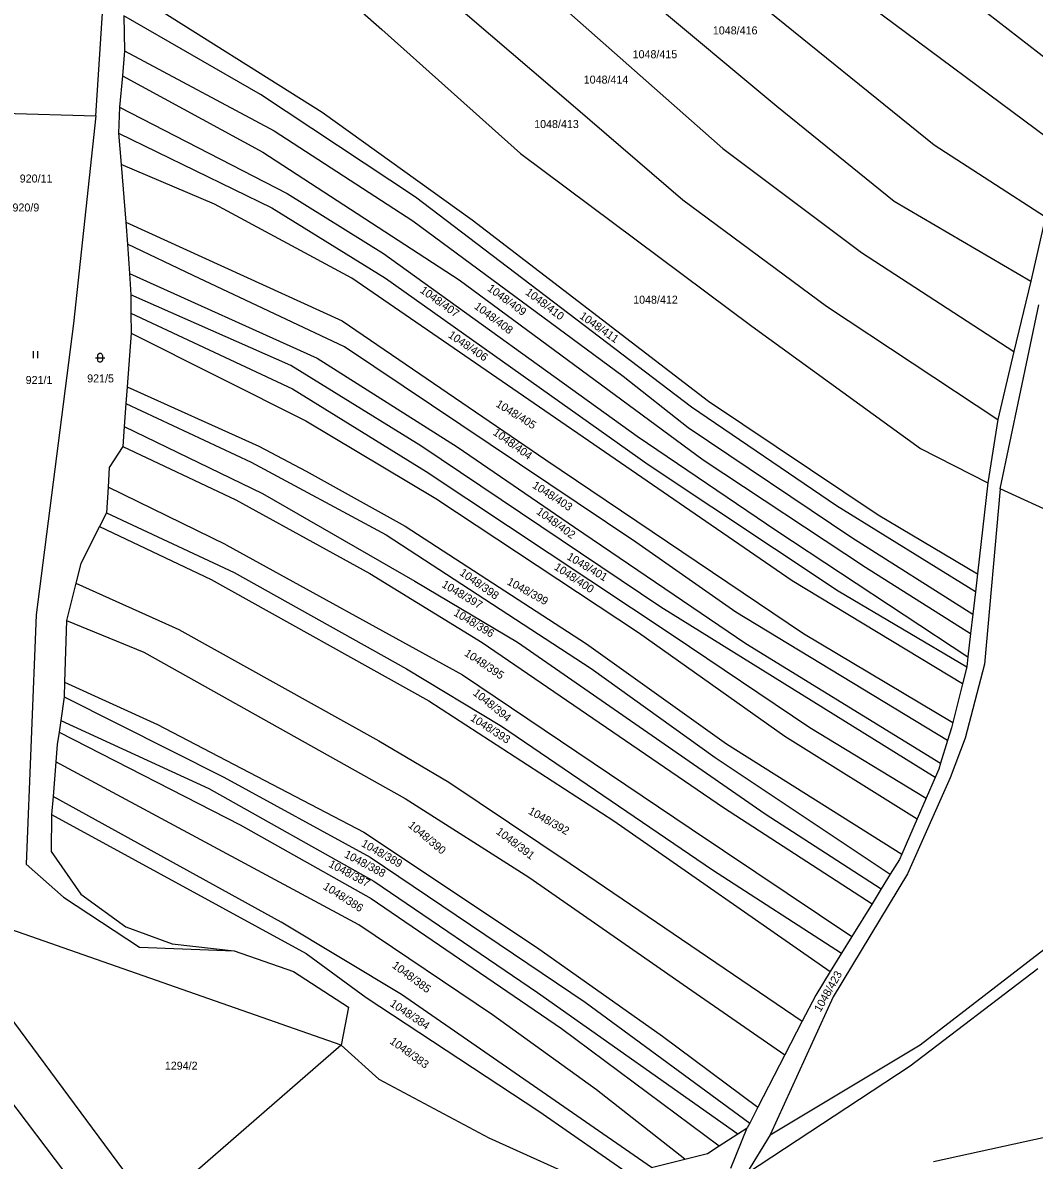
# Model space of a CAD drawing. Extents: x -580630 to -576196, y -1189024 to -1183567.
# Drawn here: x -577874.8 to -577659.8, y -1186685.8 to -1186444.2 of the extents above; entities that cross this region are included whole.
import ezdxf

# ---------------------------------------------------------------- set-up
doc = ezdxf.new("R2010")
doc.units = 0
for name, color, linetype in [('Vrstva 1', 7, 'Continuous'), ('Vrstva 16', 7, 'Continuous'), ('Vrstva 18', 7, 'Continuous'), ('Vrstva 25', 7, 'Continuous'), ('Vrstva 6', 7, 'Continuous')]:
    doc.layers.add(name, color=color, linetype=linetype)

msp = doc.modelspace()

# ---------------------------------------------------------------- linework, layer by layer
at = {"layer": 'Vrstva 1'}
for p, q in [((-577859.22, -1186463.95), (-577855.05, -1186398.23)), ((-577853.26, -1186442.7), (-577853.11, -1186450.13)), ((-577853.11, -1186450.13), (-577853.59, -1186455.45)), ((-577853.59, -1186455.45), (-577854.18, -1186462.09)), ((-577878.88, -1186463.42), (-577859.22, -1186463.95)), ((-577859.22, -1186463.95), (-577864.01, -1186508.08)), ((-577854.18, -1186462.09), (-577854.44, -1186467.67)), ((-577854.44, -1186467.67), (-577853.88, -1186474.32)), ((-577853.88, -1186474.32), (-577852.85, -1186486.55)), ((-577852.85, -1186486.55), (-577852.53, -1186491.24)), ((-577852.53, -1186491.24), (-577852.1, -1186497.48)), ((-577852.1, -1186497.48), (-577851.79, -1186501.97)), ((-577851.79, -1186501.97), (-577851.78, -1186505.89)), ((-577851.78, -1186505.89), (-577851.76, -1186510.12)), ((-577864.01, -1186508.08), (-577871.88, -1186569.94)), ((-577851.76, -1186510.12), (-577852.58, -1186521.49)), ((-577852.58, -1186521.49), (-577852.84, -1186525.09)), ((-577852.84, -1186525.09), (-577853.19, -1186529.98)), ((-577853.19, -1186529.98), (-577853.49, -1186534.17)), ((-577853.49, -1186534.17), (-577856.41, -1186538.69)), ((-577856.41, -1186538.69), (-577856.64, -1186542.85)), ((-577856.64, -1186542.85), (-577856.94, -1186548.26)), ((-577856.94, -1186548.26), (-577858.44, -1186551.22)), ((-577858.44, -1186551.22), (-577862.39, -1186559.03)), ((-577862.39, -1186559.03), (-577863.45, -1186563.21)), ((-577863.45, -1186563.21), (-577865.45, -1186571.12)), ((-577871.88, -1186569.94), (-577874.01, -1186622.9)), ((-577865.45, -1186571.12), (-577865.87, -1186584.25)), ((-577865.87, -1186584.25), (-577865.97, -1186587.39)), ((-577865.97, -1186587.39), (-577866.7, -1186592.43)), ((-577866.7, -1186592.43), (-577867.06, -1186594.9)), ((-577867.06, -1186594.9), (-577867.43, -1186597.49)), ((-577867.43, -1186597.49), (-577867.73, -1186601.18)), ((-577867.73, -1186601.18), (-577868.32, -1186608.51)), ((-577868.32, -1186608.51), (-577868.63, -1186612.38)), ((-577868.63, -1186612.38), (-577868.76, -1186620.22)), ((-577868.76, -1186620.22), (-577862.39, -1186629.26)), ((-577874.01, -1186622.9), (-577866.1, -1186629.9)), ((-577866.1, -1186629.9), (-577849.97, -1186640.56)), ((-577862.39, -1186629.26), (-577852.84, -1186636.25)), ((-577807.14, -1186661.37), (-577883.51, -1186634.65)), ((-577852.84, -1186636.25), (-577843.01, -1186639.84)), ((-577843.01, -1186639.84), (-577829.86, -1186641.3)), ((-577849.97, -1186640.56), (-577829.86, -1186641.3)), ((-577829.86, -1186641.3), (-577817.24, -1186645.69)), ((-577817.24, -1186645.69), (-577805.55, -1186653.27)), ((-577847.2, -1186696.2), (-577879.08, -1186653.13)), ((-577805.55, -1186653.27), (-577807.14, -1186661.37)), ((-577807.14, -1186661.37), (-577847.2, -1186696.2)), ((-577807.14, -1186661.37), (-577799.11, -1186668.55)), ((-577842.78, -1186718.77), (-577885, -1186663.02)), ((-577799.11, -1186668.55), (-577775.73, -1186681.05)), ((-577775.73, -1186681.05), (-577749.96, -1186692.62))]:
    msp.add_line(p, q, dxfattribs=at)
at = {"layer": 'Vrstva 25'}
for p, q in [((-577872.55, -1186513.91), (-577872.55, -1186515.41)), ((-577871.55, -1186515.41), (-577871.55, -1186513.91))]:
    msp.add_line(p, q, dxfattribs=at)
msp.add_lwpolyline([(-577858.84, -1186514.84), (-577858.74, -1186514.55), (-577858.49, -1186514.37), (-577858.18, -1186514.37), (-577857.93, -1186514.55), (-577857.83, -1186514.84), (-577857.83, -1186515.84), (-577857.93, -1186516.13), (-577858.18, -1186516.31), (-577858.49, -1186516.31), (-577858.74, -1186516.13), (-577858.84, -1186515.84)], close=True, dxfattribs=at)
msp.add_lwpolyline([(-577859.34, -1186515.34), (-577858.07, -1186515.34), (-577857.34, -1186515.34)], dxfattribs=at)
at = {"layer": 'Vrstva 6'}
for p, q in [((-577793.75, -1186395.8), (-577714.53, -1186461.91)), ((-577807.04, -1186399.23), (-577726.02, -1186470.93)), ((-577824.91, -1186404.3), (-577757.34, -1186462.16)), ((-577837.71, -1186410.74), (-577798.49, -1186445.63)), ((-577648.78, -1186458.48), (-577691.75, -1186425.18)), ((-577705.7, -1186432.42), (-577653.48, -1186471.22)), ((-577853.38, -1186436.57), (-577811.17, -1186463.18)), ((-577719.89, -1186438.75), (-577681.11, -1186470.11)), ((-577824.25, -1186459.42), (-577853.26, -1186442.7)), ((-577798.49, -1186445.63), (-577769, -1186471.95)), ((-577853.11, -1186450.13), (-577821.34, -1186467.13)), ((-577853.59, -1186455.45), (-577823.72, -1186471.65)), ((-577791.31, -1186481.22), (-577824.25, -1186459.42)), ((-577854.18, -1186462.09), (-577818.58, -1186480.43)), ((-577811.17, -1186463.18), (-577779.29, -1186486.04)), ((-577757.34, -1186462.16), (-577734.49, -1186481.83)), ((-577714.53, -1186461.91), (-577689.62, -1186482.09)), ((-577854.44, -1186467.67), (-577821.83, -1186483.53)), ((-577821.34, -1186467.13), (-577791.85, -1186486.27)), ((-577726.02, -1186470.93), (-577696.53, -1186492.99)), ((-577681.11, -1186470.11), (-577657.44, -1186485.43)), ((-577823.72, -1186471.65), (-577782.01, -1186498.77)), ((-577769, -1186471.95), (-577719.85, -1186508.64)), ((-577834.05, -1186482.73), (-577853.88, -1186474.32)), ((-577818.58, -1186480.43), (-577798.12, -1186493.19)), ((-577804.83, -1186498.41), (-577834.05, -1186482.73)), ((-577732.63, -1186525.82), (-577791.31, -1186481.22)), ((-577734.49, -1186481.83), (-577703.98, -1186504.37)), ((-577689.62, -1186482.09), (-577660.59, -1186499.11)), ((-577821.83, -1186483.53), (-577797.66, -1186498.41)), ((-577657.44, -1186485.43), (-577660.59, -1186499.11)), ((-577852.85, -1186486.55), (-577806.9, -1186507.49)), ((-577791.85, -1186486.27), (-577747.21, -1186519.23)), ((-577779.29, -1186486.04), (-577729.08, -1186524.58)), ((-577838.55, -1186497.88), (-577852.53, -1186491.24)), ((-577696.53, -1186492.99), (-577664.17, -1186513.99)), ((-577798.12, -1186493.19), (-577744.19, -1186532)), ((-577852.1, -1186497.48), (-577812.24, -1186515.43)), ((-577806.4, -1186513.04), (-577838.55, -1186497.88)), ((-577711.31, -1186562.75), (-577804.83, -1186498.41)), ((-577797.66, -1186498.41), (-577741.87, -1186538.02)), ((-577782.01, -1186498.77), (-577730.2, -1186537.05)), ((-577660.59, -1186499.11), (-577664.17, -1186513.99)), ((-577817.82, -1186517.02), (-577851.79, -1186501.97)), ((-577703.98, -1186504.37), (-577667.54, -1186528.43)), ((-577667.06, -1186543.16), (-577658.85, -1186504.08)), ((-577851.78, -1186505.89), (-577817.45, -1186521.95)), ((-577806.9, -1186507.49), (-577763.6, -1186537)), ((-577719.85, -1186508.64), (-577684.01, -1186534.64)), ((-577851.76, -1186510.12), (-577814.59, -1186528.76)), ((-577744.5, -1186554.51), (-577806.4, -1186513.04)), ((-577664.17, -1186513.99), (-577667.54, -1186528.43)), ((-577790.19, -1186534.04), (-577817.82, -1186517.02)), ((-577812.24, -1186515.43), (-577782.49, -1186534.3)), ((-577747.21, -1186519.23), (-577733.4, -1186530.13)), ((-577852.58, -1186521.49), (-577824.61, -1186534.09)), ((-577817.45, -1186521.95), (-577789.02, -1186539.49)), ((-577852.84, -1186525.09), (-577826.23, -1186537.52)), ((-577701.82, -1186546.82), (-577732.63, -1186525.82)), ((-577729.08, -1186524.58), (-577693.03, -1186548.72)), ((-577814.59, -1186528.76), (-577786.96, -1186545.24)), ((-577667.54, -1186528.43), (-577669.71, -1186541.89)), ((-577853.19, -1186529.98), (-577823.83, -1186544.17)), ((-577733.4, -1186530.13), (-577698.6, -1186553.52)), ((-577853.49, -1186534.17), (-577829.46, -1186545.51)), ((-577824.61, -1186534.09), (-577814.52, -1186539.41)), ((-577739.18, -1186568.33), (-577790.19, -1186534.04)), ((-577744.19, -1186532), (-577714.5, -1186552.11)), ((-577782.49, -1186534.3), (-577757.52, -1186551.32)), ((-577684.01, -1186534.64), (-577669.71, -1186541.89)), ((-577826.23, -1186537.52), (-577797.53, -1186552.94)), ((-577763.6, -1186537), (-577708.9, -1186573.91)), ((-577741.87, -1186538.02), (-577701.48, -1186564.87)), ((-577730.2, -1186537.05), (-577695.69, -1186559.84)), ((-577814.52, -1186539.41), (-577793.53, -1186551.1)), ((-577789.02, -1186539.49), (-577736.74, -1186574.2)), ((-577831.54, -1186555.06), (-577856.64, -1186542.85)), ((-577669.71, -1186541.89), (-577671.91, -1186561.24)), ((-577667.06, -1186543.16), (-577670.44, -1186580.46)), ((-577620.3, -1186564.71), (-577667.06, -1186543.16)), ((-577829.46, -1186545.51), (-577801.04, -1186561.19)), ((-577823.83, -1186544.17), (-577791.42, -1186562.77)), ((-577786.96, -1186545.24), (-577743.92, -1186573.69)), ((-577856.94, -1186548.26), (-577829.87, -1186560.93)), ((-577672.35, -1186565.07), (-577701.82, -1186546.82)), ((-577793.53, -1186551.1), (-577755.01, -1186576.08)), ((-577693.03, -1186548.72), (-577671.91, -1186561.24)), ((-577858.44, -1186551.22), (-577834.73, -1186562.44)), ((-577797.53, -1186552.94), (-577753.97, -1186581.37)), ((-577757.52, -1186551.32), (-577721.12, -1186576.04)), ((-577714.5, -1186552.11), (-577673.92, -1186578.85)), ((-577698.6, -1186553.52), (-577672.89, -1186569.79)), ((-577831.54, -1186555.06), (-577781.33, -1186582.7)), ((-577723.24, -1186569.39), (-577744.5, -1186554.51)), ((-577695.69, -1186559.84), (-577673.36, -1186573.92)), ((-577834.73, -1186562.44), (-577788.51, -1186588.22)), ((-577829.87, -1186560.93), (-577793.21, -1186581.4)), ((-577801.04, -1186561.19), (-577777.13, -1186575.81)), ((-577791.42, -1186562.77), (-577769.64, -1186575.79)), ((-577675.07, -1186584.61), (-577711.31, -1186562.75)), ((-577671.91, -1186561.24), (-577672.35, -1186565.07)), ((-577863.45, -1186563.21), (-577841.61, -1186573.07)), ((-577701.48, -1186564.87), (-577674.16, -1186580.99)), ((-577672.35, -1186565.07), (-577672.89, -1186569.79)), ((-577680.91, -1186604.51), (-577739.18, -1186568.33)), ((-577678.24, -1186596.62), (-577723.24, -1186569.39)), ((-577672.89, -1186569.79), (-577673.36, -1186573.92)), ((-577865.45, -1186571.12), (-577849.05, -1186577.86)), ((-577841.61, -1186573.07), (-577799.11, -1186596.73)), ((-577743.92, -1186573.69), (-577712.83, -1186595.75)), ((-577736.74, -1186574.2), (-577707.52, -1186593.86)), ((-577708.9, -1186573.91), (-577677.14, -1186592.83)), ((-577673.36, -1186573.92), (-577673.92, -1186578.85)), ((-577777.13, -1186575.81), (-577725.85, -1186610.9)), ((-577769.64, -1186575.79), (-577717.04, -1186612.2)), ((-577755.01, -1186576.08), (-577725.26, -1186597.34)), ((-577721.12, -1186576.04), (-577679.75, -1186601.49)), ((-577849.05, -1186577.86), (-577793.53, -1186608.95)), ((-577673.92, -1186578.85), (-577674.16, -1186580.99)), ((-577793.21, -1186581.4), (-577773.02, -1186593.62)), ((-577753.97, -1186581.37), (-577727.67, -1186600.24)), ((-577674.16, -1186580.99), (-577675.07, -1186584.61)), ((-577670.44, -1186580.46), (-577674.52, -1186596.14)), ((-577865.87, -1186584.25), (-577846.13, -1186593.27)), ((-577781.33, -1186582.7), (-577732.71, -1186615.38)), ((-577675.07, -1186584.61), (-577677.14, -1186592.83)), ((-577865.97, -1186587.39), (-577832.05, -1186604.43)), ((-577788.51, -1186588.22), (-577749.19, -1186613.73)), ((-577866.7, -1186592.43), (-577835.24, -1186606.82)), ((-577846.13, -1186593.27), (-577802.29, -1186616.12)), ((-577773.02, -1186593.62), (-577728.21, -1186624.09)), ((-577707.52, -1186593.86), (-577682.81, -1186608.89)), ((-577677.41, -1186593.92), (-577678.24, -1186596.62)), ((-577677.14, -1186592.83), (-577677.41, -1186593.92)), ((-577867.06, -1186594.9), (-577828.59, -1186614.53)), ((-577799.11, -1186596.73), (-577784.23, -1186605.49)), ((-577712.83, -1186595.75), (-577684.72, -1186613.27)), ((-577678.24, -1186596.62), (-577679.75, -1186601.49)), ((-577674.52, -1186596.14), (-577677.68, -1186604.57)), ((-577725.26, -1186597.34), (-577687.99, -1186620.81)), ((-577803.36, -1186635.79), (-577867.73, -1186601.18)), ((-577727.67, -1186600.24), (-577690.42, -1186625.07)), ((-577679.75, -1186601.49), (-577680.13, -1186602.71)), ((-577680.13, -1186602.71), (-577680.91, -1186604.51)), ((-577832.05, -1186604.43), (-577800.97, -1186621.44)), ((-577784.23, -1186605.49), (-577758.46, -1186622.77)), ((-577677.68, -1186604.57), (-577686.77, -1186624.98)), ((-577680.91, -1186604.51), (-577682.81, -1186608.89)), ((-577819.83, -1186635.22), (-577868.32, -1186608.51)), ((-577835.24, -1186606.82), (-577800.17, -1186626.49)), ((-577793.53, -1186608.95), (-577767.23, -1186625.69)), ((-577682.81, -1186608.89), (-577684.72, -1186613.27)), ((-577725.85, -1186610.9), (-577694.29, -1186631.33)), ((-577868.63, -1186612.38), (-577814.51, -1186641.9)), ((-577749.19, -1186613.73), (-577703.18, -1186645.69)), ((-577717.04, -1186612.2), (-577692.34, -1186628.17)), ((-577684.72, -1186613.27), (-577687.99, -1186620.81)), ((-577828.59, -1186614.53), (-577800.7, -1186630.21)), ((-577802.29, -1186616.12), (-577765.63, -1186640.57)), ((-577732.71, -1186615.38), (-577698.6, -1186638.3)), ((-577687.99, -1186620.81), (-577688.48, -1186621.93)), ((-577800.97, -1186621.44), (-577755.27, -1186652.26)), ((-577758.46, -1186622.77), (-577709.14, -1186656.26)), ((-577688.48, -1186621.93), (-577690.42, -1186625.07)), ((-577684.08, -1186661.26), (-577632.87, -1186621.83)), ((-577767.23, -1186625.69), (-577733.49, -1186649.08)), ((-577728.21, -1186624.09), (-577700.8, -1186641.85)), ((-577686.77, -1186624.98), (-577702.56, -1186651.06)), ((-577690.42, -1186625.07), (-577692.34, -1186628.17)), ((-577800.17, -1186626.49), (-577765.37, -1186650.14)), ((-577692.34, -1186628.17), (-577694.29, -1186631.33)), ((-577800.7, -1186630.21), (-577760.32, -1186657.85)), ((-577694.29, -1186631.33), (-577698.6, -1186638.3)), ((-577794.32, -1186650.63), (-577819.83, -1186635.22)), ((-577774.93, -1186654.92), (-577803.36, -1186635.79)), ((-577698.6, -1186638.3), (-577700.8, -1186641.85)), ((-577814.51, -1186641.9), (-577801.76, -1186651.2)), ((-577765.63, -1186640.57), (-577738.8, -1186659.44)), ((-577700.8, -1186641.85), (-577703.18, -1186645.69)), ((-577686.2, -1186665.78), (-577659.08, -1186645.09)), ((-577703.18, -1186645.69), (-577706.28, -1186650.71)), ((-577765.37, -1186650.14), (-577722.79, -1186680.21)), ((-577733.49, -1186649.08), (-577712.83, -1186663.42)), ((-577801.76, -1186651.2), (-577765.1, -1186675.38)), ((-577741.15, -1186687.36), (-577794.32, -1186650.63)), ((-577755.27, -1186652.26), (-577720.3, -1186677.94)), ((-577702.56, -1186651.06), (-577715.96, -1186680.39)), ((-577706.28, -1186650.71), (-577709.14, -1186656.26)), ((-577752.88, -1186670.87), (-577774.93, -1186654.92)), ((-577709.14, -1186656.26), (-577712.83, -1186663.42)), ((-577760.32, -1186657.85), (-577726.76, -1186682.77)), ((-577738.8, -1186659.44), (-577718.56, -1186674.56)), ((-577715.96, -1186680.39), (-577684.08, -1186661.26)), ((-577712.83, -1186663.42), (-577718.56, -1186674.56)), ((-577721, -1186688.63), (-577686.2, -1186665.78)), ((-577734.08, -1186685.59), (-577752.88, -1186670.87)), ((-577765.1, -1186675.38), (-577744.92, -1186689.43)), ((-577718.56, -1186674.56), (-577720.3, -1186677.94)), ((-577630.52, -1186675), (-577681.26, -1186686.16)), ((-577724.3, -1186687.49), (-577720.82, -1186678.94)), ((-577722.79, -1186680.21), (-577720.82, -1186678.94)), ((-577720.3, -1186677.94), (-577720.82, -1186678.94)), ((-577726.76, -1186682.77), (-577722.79, -1186680.21)), ((-577715.96, -1186680.39), (-577721, -1186688.63)), ((-577729.24, -1186684.38), (-577726.76, -1186682.77)), ((-577741.15, -1186687.36), (-577734.08, -1186685.59)), ((-577734.08, -1186685.59), (-577729.24, -1186684.38))]:
    msp.add_line(p, q, dxfattribs=at)

# ---------------------------------------------------------------- texts
at = {"layer": 'Vrstva 16'}
for s, p in [('920/11', (-577875.407, -1186478.12)), ('920/9', (-577876.944, -1186484.27))]:
    msp.add_text(s, height=1.7, dxfattribs=at).set_placement(p)
at = {"layer": 'Vrstva 18'}
for s, p in [('1048/416', (-577728.128, -1186446.66)), ('1048/415', (-577745.175, -1186451.72)), ('1048/414', (-577755.568, -1186457.11)), ('1048/413', (-577766.096, -1186466.55)), ('1048/412', (-577745.062, -1186503.86)), ('921/1', (-577874.151, -1186520.92)), ('921/5', (-577861.076, -1186520.58)), ('1294/2', (-577844.572, -1186666.57))]:
    msp.add_text(s, height=1.7, dxfattribs=at).set_placement(p)
for s, rotation, p in [('1048/407', 324.29411, (-577790.487, -1186501.339)), ('1048/409', 323.77845, (-577776.182, -1186500.938)), ('1048/410', 322.74713, (-577768.098, -1186501.743)), ('1048/408', 322.97631, (-577778.984, -1186504.727)), ('1048/411', 324.75248, (-577756.614, -1186506.817)), ('1048/406', 325.89839, (-577784.523, -1186510.876)), ('1048/405', 328.01834, (-577774.389, -1186525.583)), ('1048/404', 324.29411, (-577775, -1186531.556)), ('1048/403', 327.10161, (-577766.627, -1186542.84)), ('1048/402', 324.06493, (-577765.787, -1186548.346)), ('1048/401', 329.27884, (-577759.3, -1186558.044)), ('1048/398', 324.75248, (-577782.089, -1186561.343)), ('1048/400', 326.41406, (-577762.002, -1186560.18)), ('1048/397', 329.39344, (-577785.881, -1186563.945)), ('1048/399', 331.11231, (-577772.015, -1186563.393)), ('1048/396', 328.99237, (-577783.367, -1186569.963)), ('1048/395', 326.24217, (-577781.08, -1186578.482)), ('1048/394', 321.08555, (-577779.239, -1186586.815)), ('1048/393', 327.2162, (-577779.824, -1186592.257)), ('1048/392', 330.53935, (-577767.503, -1186612.11)), ('1048/390', 320.16882, (-577793.016, -1186614.872)), ('1048/391', 322.68983, (-577774.343, -1186616.292)), ('1048/389', 330.13828, (-577802.974, -1186619.001)), ('1048/388', 332.08634, (-577806.609, -1186621.34)), ('1048/387', 331.97175, (-577809.921, -1186623.389)), ('1048/386', 327.50268, (-577811.097, -1186628.062)), ('1048/385', 323.26279, (-577796.431, -1186644.73)), ('1048/423', 60.44705, (-577705.267, -1186654.459)), ('1048/384', 326.24217, (-577796.893, -1186652.904)), ('1048/383', 324.17952, (-577796.935, -1186660.865))]:
    msp.add_text(s, height=1.7, rotation=rotation, dxfattribs=at).set_placement(p)

doc.saveas('drawing.dxf')
